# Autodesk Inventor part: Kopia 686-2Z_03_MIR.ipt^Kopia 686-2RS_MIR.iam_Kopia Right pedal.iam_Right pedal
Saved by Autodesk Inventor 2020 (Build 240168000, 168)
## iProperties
Created: 2017-10
Part Number: Kopia 686-2Z_03_MIR.ipt^Kopia 686-2RS_MIR.iam_Kopia Right pedal.iam_Right pedal
Material: Ogólny
Document SubType Name: Modeling
Designer: Tomasz
Density: 1 g/cm^3
Appearance: Domyślna
Sending System: SolidWorks 2017
Last Author: Tomasz
Last Saved: 2017-10-01
Author: Tomasz
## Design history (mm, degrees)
